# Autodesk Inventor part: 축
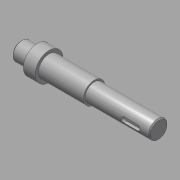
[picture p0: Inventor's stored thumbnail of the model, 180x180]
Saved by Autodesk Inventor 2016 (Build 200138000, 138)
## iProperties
Created: 2015-09
Part Number: 축
Material: 강철, 연강
Document SubType Name: Modeling
Designer: mduedu
Density: 7.86 g/cm^3
Mass: 263.424 g
Surface Area: 86.4309 cm^2
Volume: 33.5145 cm^3
Appearance: 강철
Author: mduedu
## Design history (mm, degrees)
sketch "스케치1"
  geometry: L1 (-69, 0)-(69, 0); L2 (-69, 0)-(-69, 8.5); L3 (-69, 8.5)-(-54, 8.5); L4 (-54, 8.5)-(-54, 13); L5 (-54, 13)-(-43, 13); L6 (-43, 13)-(-43, 10); L7 (-43, 10)-(-1, 10); L8 (-1, 10)-(-1, 8.5); L9 (-1, 8.5)-(69, 8.5); L10 (69, 8.5)-(69, 0); 2 further points
  constraints: 20 end point, 5 parallel, 2 horizontal, 2 perpendicular, 1 coincident, 1 midpoint, 1 vertical
  dimensions: "d0" = 138 distance of L1.start L1.end; "d2" = 11 distance of L4.end L5.end; "d3" = 42 distance of L6.end L7.end; "d4" = 70 distance of L8.end L9.end; "d5" = 17 diameter of L3 L1; "d6" = 17 diameter of L9 L1; "d7" = 20 diameter of L7 L1; "d8" = 26 diameter of L5 L1
revolve "회전1" sketch "스케치1" stored, may be unused: angle "d9" = 90 deg
node "작업 평면1"
sketch "스케치2"
  geometry: L1 (10.5, 2.5)-(23.5, 2.5); L2 (23.5, -2.5)-(10.5, -2.5); L3 (10.5, 2.5)-(23.5, -2.5); L4 (23.5, 2.5)-(10.5, -2.5); L5 (35, -8.5)-(35, 8.5) reference; A1 r 2.5 centre (10.5, 0) between (10.5, 2.5) and (10.5, -2.5); A2 r 2.5 centre (23.5, 0) between (23.5, -2.5) and (23.5, 2.5); 2 further points
  constraints: 8 end point, 4 point on circle, 4 tangent, 2 centre point, 2 midpoint, 1 horizontal, 1 horizontal alignment, 1 parallel
  dimensions: "d10" = 18 dimension on A2 A1; "d12" = 9 distance edge to line of A2 L5; "d13" = 5 distance between parallel lines of L2 L1
extrude "돌출1" cut sketch "스케치2" distance "d14" = 3; taper "d15" = 0 deg
node "작업 평면2"
sketch "스케치4"
  geometry: L1 (7, -3)-(-9, -3); L2 (-9, 3)-(7, 3); L3 (-21, 10)-(-21, -10) reference; A1 r 3 centre (-9, 0) between (-9, 3) and (-9, -3); A2 r 3 centre (7, 0) between (7, -3) and (7, 3); 1 further point
  constraints: 4 end point, 4 point on circle, 4 tangent, 2 centre point, 1 horizontal, 1 horizontal alignment, 1 parallel
  dimensions: "d16" = 22 dimension on A1 A2; "d18" = 6 distance between parallel lines of L2 L1; "d19" = 9 distance edge to line of A1 L3
extrude "돌출2" cut sketch "스케치4" distance "d20" = 3.5; taper "d21" = 0 deg
sketch "스케치5"
  geometry: L1 (-1, 8.5)-(69, 8.5) reference; L2 (-1, -8.5)-(69, -8.5) reference; L3 (42, 8.5)-(42, -8.5); L4 (42, -6.5)-(40, -8.5); L5 (42, -8.5)-(40, -8.5); L6 (42, -8.5)-(42, -6.5); L7 (-1, -10)-(-1, 10) reference; 1 further point
  constraints: 8 end point, 4 point on line, 1 collinear, 1 perpendicular
  dimensions: "d22" = 4 diameter of L4.end L3; "d24" = 45 deg angle of L3 L4; "d26" = 43 distance between parallel lines of L3 L7
revolve "회전2" sketch "스케치5" stored, may be unused: angle "d27" = 90 deg
chamfer "모따기1" distance "d28" = 1; stored, may be unused: second distance "d29" = 2, angle "d30" = 45 deg
sketch "스케치6"
  geometry: L1 (42, -6.5)-(40, -8.5) reference; L2 (42, -6.5)-(44, -8.5) reference; 2 further points
  constraints: 1 coincident
node "솔리드1"
